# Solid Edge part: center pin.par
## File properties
Author: Binay
Template: sync ansi part.par
Last saved by: Cadcim
Revision: 3
Application: Solid Edge
Accuracy: 0.990
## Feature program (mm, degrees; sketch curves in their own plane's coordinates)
sketch for "unnamed Hole 1" plane through (42.6694, 3.8175, 49.1782) normal (0, 0, 1) x-axis (1, 0, 0)
  hole centre (0.7149, -3.8175) bore radius 8.001
hole "unnamed Hole 1" through
pattern "unnamed Pattern 1" of "unnamed Hole 1"
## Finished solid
Body 1: solid body, 7 faces, 7 edges, 0 vertices.
  Faces by surface: cylinder 3, plane 3, cone 1
  Edges by curve: circle 7
Bounding box of the edges (mm): 34.290 x 34.290 x 76.200, from (26.2393, -17.145, -27.0218) to (60.5293, 17.145, 49.1782).
Cylindrical faces by radius (mm): R8.001 x1, R12.7 x1, R17.145 x1
Conical faces (half-angle, radius in mm at the cone's reference point): 45 deg R11.176 x1
Planar faces by outward normal: +z 1, -z 2
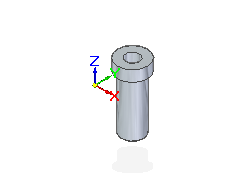
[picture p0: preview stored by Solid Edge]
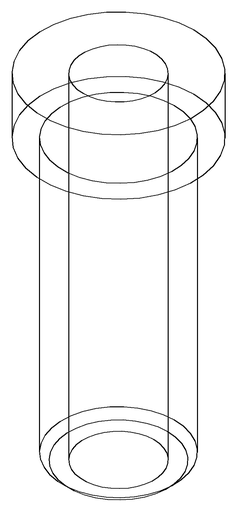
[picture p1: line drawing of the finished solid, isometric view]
